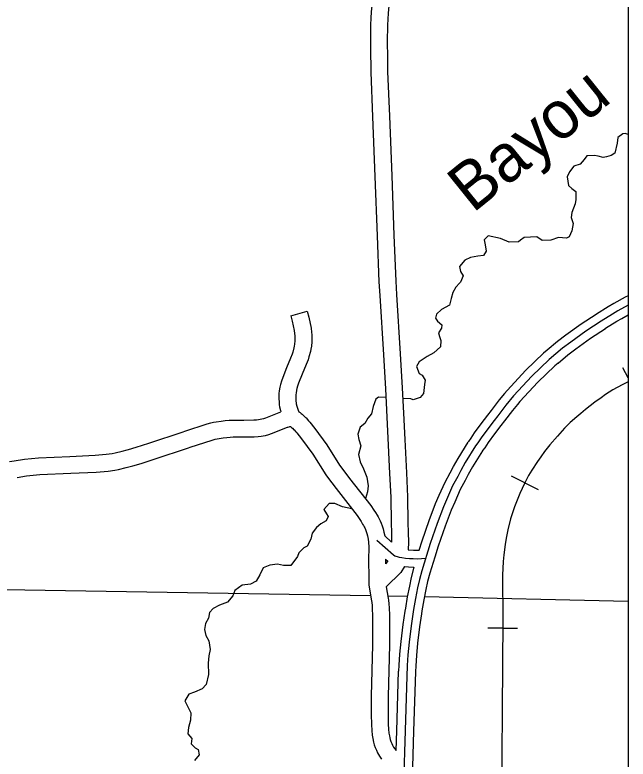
# Model space of a CAD drawing. Extents: x 1373094 to 1376427, y 1168361 to 1170494.
# Drawn here: x 1373889.9 to 1373980.6, y 1170144.1 to 1170254.2 of the extents above; entities that cross this region are included whole.
import ezdxf

# ---------------------------------------------------------------- set-up
doc = ezdxf.new("R2010")
doc.units = 0
doc.layers.add('R_Axis', color=7, linetype='Continuous')
doc.layers.add('R_No Plot', color=7, linetype='Continuous')

msp = doc.modelspace()

# ---------------------------------------------------------------- linework, layer by layer
at = {"layer": 'R_Axis'}
for p, q in [((1373930.68, 1170209.71), (1373933.09, 1170210.4)), ((1373977.22, 1170207.84), (1373977.22, 1170207.84)), ((1373980.59, 1170200.54), (1373979.83, 1170202.04)), ((1373965.3, 1170185), (1373963.34, 1170186)), ((1373965.3, 1170185), (1373967.26, 1170184)), ((1373962.04, 1170163.51), (1373959.84, 1170163.53)), ((1373962.04, 1170163.51), (1373964.24, 1170163.5))]:
    msp.add_line(p, q, dxfattribs=at)
for points in [[(1373942.8, 1170256.88), (1373942.59, 1170254.68), (1373942.53, 1170253.73), (1373942.48, 1170252.76), (1373942.46, 1170250.25), (1373942.48, 1170247.97)], [(1373945.29, 1170256.65), (1373945.08, 1170254.48), (1373945.02, 1170253.58), (1373944.98, 1170252.69), (1373944.96, 1170250.25), (1373944.98, 1170247.99)], [(1373942.48, 1170247.97), (1373942.48, 1170247.91), (1373942.5, 1170247.2), (1373942.51, 1170246.54), (1373942.51, 1170245.78), (1373942.77, 1170239.13)], [(1373944.98, 1170247.99), (1373944.98, 1170247.94), (1373944.99, 1170247.25), (1373945.01, 1170246.57), (1373945.01, 1170245.83), (1373945.27, 1170239.23)], [(1373945.27, 1170239.23), (1373945.61, 1170230.44)], [(1373942.77, 1170239.13), (1373943.11, 1170230.34)], [(1373980.59, 1170236.56), (1373980.17, 1170236.68), (1373979.82, 1170236.61), (1373979.08, 1170236.08), (1373978.95, 1170235.24), (1373978.63, 1170233.75), (1373978.09, 1170233.42), (1373977.38, 1170233.23), (1373976.88, 1170233.11), (1373976.16, 1170233.31), (1373975.63, 1170233.45), (1373974.46, 1170233.39), (1373974.09, 1170232.82), (1373973.49, 1170232.13), (1373972.55, 1170231.83), (1373971.92, 1170231.03), (1373971.58, 1170230.26), (1373971.79, 1170228.99), (1373972.25, 1170228.53), (1373972.84, 1170228.09), (1373972.83, 1170226.94), (1373972.78, 1170226.27), (1373972.24, 1170225.02), (1373972.17, 1170224.27), (1373972.46, 1170223.37), (1373972.28, 1170222.29), (1373971.87, 1170221.42), (1373971.49, 1170221.2), (1373970.29, 1170221.29), (1373969.18, 1170220.9), (1373967.89, 1170220.86), (1373967.08, 1170221.41), (1373965.2, 1170221.32), (1373964.69, 1170220.92), (1373964.35, 1170220.65), (1373962.97, 1170220.6), (1373961.72, 1170221.13), (1373959.88, 1170221.54), (1373959.31, 1170220.95), (1373959.43, 1170220.23), (1373959.6, 1170219.3), (1373959.18, 1170218.64), (1373958.33, 1170218.52), (1373957.26, 1170218.33), (1373956.43, 1170217.93), (1373955.64, 1170217.03), (1373955.8, 1170216.26), (1373956.2, 1170215.65), (1373955.8, 1170214.71), (1373955.62, 1170214.55), (1373955.09, 1170213.94), (1373954.65, 1170213.16), (1373954.42, 1170212.29), (1373954.14, 1170211.3), (1373952.97, 1170210.67), (1373952.22, 1170209.97), (1373952.07, 1170209.37), (1373952.38, 1170208.94), (1373953.01, 1170208.37), (1373953, 1170207.88), (1373952.55, 1170207.21), (1373952.66, 1170206.67), (1373952.87, 1170206.04), (1373952.81, 1170205.12), (1373951.85, 1170204.23), (1373950.88, 1170203.71)], [(1373945.61, 1170230.44), (1373945.95, 1170221.64)], [(1373943.11, 1170230.34), (1373943.45, 1170221.55)], [(1373945.95, 1170221.64), (1373946.21, 1170214.85), (1373946.33, 1170212.88)], [(1373943.45, 1170221.55), (1373943.72, 1170214.72), (1373943.84, 1170212.73)], [(1373946.33, 1170212.88), (1373946.87, 1170204.1)], [(1373943.84, 1170212.73), (1373944.38, 1170203.94)], [(1373980.59, 1170212.68), (1373980.15, 1170212.46), (1373978.47, 1170211.52), (1373977.63, 1170211.05), (1373975.9, 1170209.97), (1373975.84, 1170209.93)], [(1373980.59, 1170211.27), (1373979.08, 1170210.43), (1373978.27, 1170209.98), (1373976.58, 1170208.92), (1373974.33, 1170207.43), (1373972.12, 1170205.84), (1373970.9, 1170204.93), (1373968.92, 1170203.24), (1373966.35, 1170200.8), (1373963.63, 1170197.86), (1373962.5, 1170196.5), (1373961.31, 1170194.94), (1373960.78, 1170194.24), (1373959.82, 1170192.99), (1373958.85, 1170191.68), (1373958.34, 1170190.92), (1373958.01, 1170190.46), (1373956.5, 1170188), (1373955.84, 1170186.82), (1373955.38, 1170185.93), (1373954.63, 1170184.57), (1373953.25, 1170181.46), (1373952.35, 1170179.01), (1373951.31, 1170176.03), (1373950.05, 1170171.99), (1373949.71, 1170170.7), (1373949.44, 1170169.48), (1373949.13, 1170167.91), (1373948.86, 1170166.25), (1373948.49, 1170163.88), (1373948.18, 1170161.43), (1373948.01, 1170159.59), (1373947.92, 1170158), (1373947.05, 1170130.79)], [(1373930.68, 1170209.71), (1373930.9, 1170208.94), (1373931.2, 1170207.52), (1373931.24, 1170207.09), (1373931.27, 1170206.73), (1373931.29, 1170206.4), (1373931.28, 1170206), (1373931.24, 1170205.53), (1373931.19, 1170205.25), (1373931.14, 1170204.98), (1373930.97, 1170204.35), (1373930.86, 1170204.03), (1373930.64, 1170203.44), (1373930.05, 1170202.02)], [(1373933.09, 1170210.4), (1373933.33, 1170209.54), (1373933.68, 1170207.9), (1373933.74, 1170207.31), (1373933.77, 1170206.89), (1373933.79, 1170206.44), (1373933.78, 1170205.87), (1373933.72, 1170205.21), (1373933.65, 1170204.8), (1373933.58, 1170204.42), (1373933.36, 1170203.63), (1373933.23, 1170203.21), (1373932.96, 1170202.52), (1373932.37, 1170201.07)], [(1373975.84, 1170209.93), (1373973.62, 1170208.46), (1373971.38, 1170206.85), (1373970.12, 1170205.91), (1373968.63, 1170204.63)], [(1373977.22, 1170207.84), (1373977.25, 1170207.87), (1373978.91, 1170208.9), (1373979.68, 1170209.34), (1373980.59, 1170209.84)], [(1373970.25, 1170202.73), (1373971.69, 1170203.95), (1373972.86, 1170204.83), (1373975.04, 1170206.4), (1373977.22, 1170207.84)], [(1373946.87, 1170204.1), (1373947.18, 1170199.07), (1373947.37, 1170195.3)], [(1373968.63, 1170204.63), (1373968.09, 1170204.17), (1373965.46, 1170201.68), (1373962.69, 1170198.69), (1373962.31, 1170198.23)], [(1373944.38, 1170203.94), (1373944.68, 1170198.93), (1373945.29, 1170186.39)], [(1373950.88, 1170203.71), (1373949.69, 1170202.9), (1373949.26, 1170202.22), (1373949.68, 1170201.18), (1373950.12, 1170200.92), (1373950.58, 1170200.2), (1373950.48, 1170199.54), (1373950.33, 1170198.24), (1373949.84, 1170197.63), (1373948.78, 1170197.27), (1373948.44, 1170197.46), (1373947.26, 1170197.5)], [(1373930.05, 1170202.02), (1373929.48, 1170200.61), (1373929.28, 1170200.03), (1373929.15, 1170199.58), (1373929.07, 1170199.18), (1373928.97, 1170198.63), (1373928.93, 1170198.21), (1373928.92, 1170197.47), (1373928.95, 1170196.93), (1373928.98, 1170196.57), (1373929.03, 1170196.23), (1373929.15, 1170195.73), (1373929.21, 1170195.52)], [(1373970.25, 1170202.73), (1373969.76, 1170202.31), (1373967.24, 1170199.92), (1373964.57, 1170197.04), (1373964.23, 1170196.62)], [(1373932.37, 1170201.07), (1373931.82, 1170199.73), (1373931.67, 1170199.29), (1373931.58, 1170198.98), (1373931.52, 1170198.71), (1373931.45, 1170198.28), (1373931.43, 1170198.06), (1373931.42, 1170197.53), (1373931.44, 1170197.1), (1373931.46, 1170196.86), (1373931.49, 1170196.71), (1373931.56, 1170196.37), (1373931.66, 1170196.05), (1373931.78, 1170195.74), (1373931.88, 1170195.49)], [(1373980.59, 1170199.96), (1373979.73, 1170199.52), (1373978.33, 1170198.76), (1373977.25, 1170198.06), (1373976.59, 1170197.6), (1373975.66, 1170196.92), (1373974.97, 1170196.41), (1373974.28, 1170195.85), (1373973.59, 1170195.28), (1373973.02, 1170194.79), (1373972.04, 1170193.92), (1373971.17, 1170193.09), (1373970.13, 1170191.93), (1373969.01, 1170190.63), (1373968.23, 1170189.65), (1373967.67, 1170188.87), (1373967.16, 1170188.15), (1373966.32, 1170186.88), (1373965.85, 1170186.08), (1373965.27, 1170184.93), (1373964.58, 1170183.43), (1373963.78, 1170181.44), (1373963.2, 1170179.68), (1373962.79, 1170178.08), (1373962.54, 1170176.84), (1373962.38, 1170175.91), (1373962.2, 1170174.35), (1373962.11, 1170173.36), (1373961.98, 1170171.34), (1373962.05, 1170164.74), (1373961.81, 1170131.3)], [(1373980.59, 1170199.96), (1373979.73, 1170199.52), (1373978.33, 1170198.76), (1373977.25, 1170198.06), (1373976.59, 1170197.6), (1373975.66, 1170196.92), (1373974.97, 1170196.41), (1373974.28, 1170195.85)], [(1373944.75, 1170197.62), (1373943.65, 1170197.7), (1373943.25, 1170197.39), (1373942.86, 1170196.29), (1373942.63, 1170195.22), (1373942.07, 1170194.56), (1373941.63, 1170193.78), (1373940.93, 1170193.26), (1373940.62, 1170192.2), (1373940.77, 1170191.41), (1373941.02, 1170190.46), (1373940.7, 1170189.2), (1373940.95, 1170188.12), (1373941.46, 1170187.06), (1373941.93, 1170185.87), (1373942.13, 1170184.55), (1373942.05, 1170183.7), (1373941.71, 1170182.67)], [(1373962.31, 1170198.23), (1373961.52, 1170197.28), (1373960.32, 1170195.7), (1373959.79, 1170195), (1373958.82, 1170193.74), (1373957.83, 1170192.4), (1373957.31, 1170191.63), (1373956.97, 1170191.14), (1373956.91, 1170191.05)], [(1373964.23, 1170196.62), (1373963.47, 1170195.72), (1373962.31, 1170194.18), (1373961.77, 1170193.48), (1373960.82, 1170192.24), (1373959.87, 1170190.96), (1373959.37, 1170190.21), (1373959.06, 1170189.77), (1373959.04, 1170189.74)], [(1373923.71, 1170194.3), (1373925.2, 1170194.32), (1373925.61, 1170194.34), (1373925.91, 1170194.38), (1373926.16, 1170194.43), (1373926.4, 1170194.47), (1373926.69, 1170194.55), (1373926.98, 1170194.64), (1373929.21, 1170195.52)], [(1373931.88, 1170195.49), (1373932.05, 1170195.39), (1373932.2, 1170195.28), (1373932.37, 1170195.15), (1373932.58, 1170194.96), (1373932.88, 1170194.68)], [(1373947.37, 1170195.3), (1373947.56, 1170191.41), (1373947.79, 1170186.5)], [(1373974.28, 1170195.85), (1373973.59, 1170195.28), (1373973.02, 1170194.79), (1373972.04, 1170193.92), (1373971.17, 1170193.09), (1373970.13, 1170191.93), (1373969.01, 1170190.63), (1373968.23, 1170189.65), (1373967.67, 1170188.87), (1373967.16, 1170188.15), (1373966.32, 1170186.88), (1373965.85, 1170186.08), (1373965.27, 1170184.93), (1373964.58, 1170183.43), (1373963.78, 1170181.44), (1373963.2, 1170179.68), (1373962.79, 1170178.08), (1373962.54, 1170176.84), (1373962.38, 1170175.91), (1373962.2, 1170174.35), (1373962.11, 1170173.36), (1373961.98, 1170171.34), (1373962.05, 1170164.74), (1373961.81, 1170131.3)], [(1373914.76, 1170192.57), (1373915, 1170192.65), (1373918.31, 1170193.72), (1373918.85, 1170193.87), (1373919.22, 1170193.96), (1373919.65, 1170194.05), (1373920.37, 1170194.15), (1373920.98, 1170194.22), (1373921.54, 1170194.26), (1373922.06, 1170194.29), (1373922.81, 1170194.3), (1373923.04, 1170194.29), (1373923.29, 1170194.3), (1373923.71, 1170194.3)], [(1373932.88, 1170194.68), (1373932.95, 1170194.61), (1373933.32, 1170194.2), (1373933.5, 1170193.99), (1373934.24, 1170193.04), (1373936.01, 1170190.65), (1373937.9, 1170187.62), (1373938.1, 1170187.36)], [(1373923.74, 1170191.8), (1373925.28, 1170191.82), (1373925.84, 1170191.85), (1373926.28, 1170191.91), (1373926.6, 1170191.97), (1373926.96, 1170192.03), (1373927.41, 1170192.16), (1373927.82, 1170192.29), (1373930.2, 1170193.23), (1373930.23, 1170193.24), (1373930.42, 1170193.3), (1373930.56, 1170193.32), (1373930.59, 1170193.32), (1373930.64, 1170193.32), (1373930.68, 1170193.29), (1373930.78, 1170193.21), (1373930.91, 1170193.11), (1373931.15, 1170192.87)], [(1373906.46, 1170189.89), (1373906.65, 1170189.94), (1373907.79, 1170190.27), (1373909.68, 1170190.87), (1373914.76, 1170192.57)], [(1373931.15, 1170192.87), (1373931.16, 1170192.86), (1373931.43, 1170192.57), (1373931.55, 1170192.42), (1373932.26, 1170191.53), (1373933.94, 1170189.24), (1373935.84, 1170186.21), (1373936.1, 1170185.86)], [(1373915.55, 1170190.2), (1373915.78, 1170190.28), (1373919.03, 1170191.32), (1373919.49, 1170191.45), (1373919.77, 1170191.52), (1373920.08, 1170191.58), (1373920.68, 1170191.67), (1373921.2, 1170191.73), (1373921.7, 1170191.76), (1373922.16, 1170191.79), (1373922.77, 1170191.8), (1373923.01, 1170191.79), (1373923.33, 1170191.8), (1373923.74, 1170191.8)], [(1373952.65, 1170183.18), (1373953.51, 1170185.12), (1373954.28, 1170186.51), (1373954.74, 1170187.41), (1373955.42, 1170188.63), (1373956.91, 1170191.05)], [(1373898.01, 1170188.93), (1373901.75, 1170189.11), (1373903.37, 1170189.24), (1373904.23, 1170189.36), (1373904.7, 1170189.45), (1373905.71, 1170189.69), (1373906.46, 1170189.89)], [(1373907.1, 1170187.47), (1373907.33, 1170187.53), (1373908.52, 1170187.88), (1373910.45, 1170188.49), (1373915.55, 1170190.2)], [(1373959.04, 1170189.74), (1373957.58, 1170187.37), (1373956.94, 1170186.23), (1373956.48, 1170185.34), (1373955.76, 1170184.01), (1373954.93, 1170182.16)], [(1373889.08, 1170188.16), (1373889.77, 1170188.28), (1373891.27, 1170188.51), (1373893.35, 1170188.71), (1373898.01, 1170188.93)], [(1373898.12, 1170186.43), (1373901.9, 1170186.61), (1373903.65, 1170186.75), (1373904.63, 1170186.9), (1373905.21, 1170187), (1373906.32, 1170187.26), (1373907.1, 1170187.47)], [(1373890.18, 1170185.82), (1373891.58, 1170186.03), (1373893.53, 1170186.22), (1373898.12, 1170186.43)], [(1373938.1, 1170187.36), (1373939.37, 1170185.67), (1373942.5, 1170181.66), (1373942.98, 1170180.96), (1373943.2, 1170180.61), (1373943.44, 1170180.23)], [(1373945.29, 1170186.39), (1373945.46, 1170182.87), (1373945.52, 1170179.1), (1373945.56, 1170177.62)], [(1373947.79, 1170186.5), (1373947.96, 1170182.95), (1373948.02, 1170179.16), (1373948.06, 1170177.68)], [(1373936.1, 1170185.86), (1373937.38, 1170184.15), (1373940.48, 1170180.18), (1373940.89, 1170179.58), (1373941.09, 1170179.28), (1373941.31, 1170178.91)], [(1373949.69, 1170175.04), (1373950.13, 1170176.43), (1373951.17, 1170179.43), (1373952.09, 1170181.94), (1373952.65, 1170183.18)], [(1373939.7, 1170181.18), (1373938.35, 1170181.48), (1373937.21, 1170181.96), (1373936.38, 1170181.94), (1373935.56, 1170181.09), (1373935.96, 1170180.44), (1373936.22, 1170180.05), (1373935.93, 1170179.41), (1373935.11, 1170178.97), (1373934.47, 1170178.41), (1373933.85, 1170177.56), (1373933.64, 1170176.69), (1373933.11, 1170175.64), (1373932.62, 1170175.41), (1373931.85, 1170174.66), (1373931.68, 1170174.09), (1373930.68, 1170172.8), (1373929.61, 1170172.79), (1373928.71, 1170172.99), (1373927.6, 1170172.84), (1373926.61, 1170172.46), (1373926.11, 1170171.42), (1373925.58, 1170170.47), (1373924.71, 1170170.04), (1373923.5, 1170169.86), (1373922.4, 1170169.07), (1373922.1, 1170168.31), (1373921.31, 1170167.34), (1373920.15, 1170166.92), (1373919.21, 1170166.41), (1373918.66, 1170165.82), (1373918.49, 1170164.99), (1373918.06, 1170164.22), (1373917.91, 1170163.33), (1373918.13, 1170162.41), (1373918.55, 1170161.62), (1373918.76, 1170160.37), (1373918.53, 1170159.4), (1373918.47, 1170158.33), (1373918.52, 1170156.67), (1373918.17, 1170155.16), (1373917.58, 1170154.53), (1373916.43, 1170154.06), (1373915.57, 1170153.76), (1373914.98, 1170152.76), (1373915.9, 1170150.97), (1373915.82, 1170149.92), (1373915.53, 1170148.81), (1373915.43, 1170147.87), (1373916.03, 1170147.2), (1373915.96, 1170146.4), (1373916.54, 1170145.79), (1373916.97, 1170145.58), (1373917.12, 1170144.8), (1373916.41, 1170143.95)], [(1373954.93, 1170182.16), (1373954.41, 1170180.99), (1373953.52, 1170178.59), (1373952.5, 1170175.64), (1373951.99, 1170174.02)], [(1373943.44, 1170180.23), (1373943.6, 1170179.97), (1373943.76, 1170179.68), (1373943.89, 1170179.41), (1373944.06, 1170179.04), (1373944.21, 1170178.64), (1373944.35, 1170178.2), (1373944.47, 1170177.71), (1373944.58, 1170177.16)], [(1373941.31, 1170178.91), (1373941.44, 1170178.7), (1373941.54, 1170178.52), (1373941.63, 1170178.35), (1373941.74, 1170178.09), (1373941.85, 1170177.8), (1373941.95, 1170177.5), (1373942.03, 1170177.17), (1373942.13, 1170176.68), (1373942.19, 1170176.21), (1373942.24, 1170175.51), (1373942.19, 1170173.6), (1373942.22, 1170170.96)], [(1373945.56, 1170177.62), (1373945.6, 1170176.25)], [(1373948.06, 1170177.68), (1373948.1, 1170176.24), (1373948.07, 1170175.1)], [(1373943.41, 1170176.53), (1373945.86, 1170174.34), (1373946.07, 1170174.22), (1373946.23, 1170174.16), (1373946.42, 1170174.09), (1373946.7, 1170174.02), (1373947.09, 1170173.96), (1373947.66, 1170173.89), (1373948.22, 1170173.84), (1373948.79, 1170173.81), (1373949.38, 1170173.79), (1373950.64, 1170173.88)], [(1373944.58, 1170177.16), (1373945.6, 1170176.25)], [(1373948.07, 1170175.1), (1373948.84, 1170175.05), (1373949.69, 1170175.04)], [(1373944.68, 1170173.72), (1373945.04, 1170173.4)], [(1373944.68, 1170173.72), (1373944.69, 1170173.04)], [(1373945.04, 1170173.4), (1373944.69, 1170173.04)], [(1373951.99, 1170174.02), (1373951.25, 1170171.65), (1373950.92, 1170170.41), (1373950.67, 1170169.22), (1373950.36, 1170167.69), (1373950.09, 1170166.06), (1373950.03, 1170165.65)], [(1373947.52, 1170172.65), (1373946.94, 1170171.75), (1373944.8, 1170169.62)], [(1373947.52, 1170172.65), (1373948.12, 1170172.59), (1373948.9, 1170172.55)], [(1373948.9, 1170172.55), (1373948.49, 1170170.99), (1373948.22, 1170169.73), (1373947.9, 1170168.14), (1373947.63, 1170166.45), (1373947.56, 1170166.03)], [(1373942.22, 1170170.96), (1373942.24, 1170169.85), (1373942.6, 1170167.56), (1373942.65, 1170167.3), (1373942.7, 1170166.86), (1373942.74, 1170166.38), (1373942.76, 1170165.41), (1373942.76, 1170164.5), (1373942.77, 1170163.42), (1373942.77, 1170162.21)], [(1373870.23, 1170169.54), (1373942.48, 1170168.34)], [(1373944.8, 1170169.62), (1373945.07, 1170167.96), (1373945.12, 1170167.65), (1373945.19, 1170167.1), (1373945.23, 1170166.5), (1373945.26, 1170165.45), (1373945.26, 1170164.51), (1373945.27, 1170163.42), (1373945.27, 1170162.21)], [(1373945.02, 1170168.3), (1373947.92, 1170168.25)], [(1373950.45, 1170168.22), (1373980.59, 1170167.52)], [(1373947.56, 1170166.03), (1373947.25, 1170164.06), (1373946.94, 1170161.56), (1373946.76, 1170159.68), (1373946.67, 1170158.06), (1373946.64, 1170157.14)], [(1373950.03, 1170165.65), (1373949.73, 1170163.71), (1373949.43, 1170161.29), (1373949.26, 1170159.49), (1373949.17, 1170157.95), (1373949.14, 1170157.06)], [(1373942.77, 1170162.21), (1373942.77, 1170161.06), (1373942.59, 1170153.44)], [(1373945.27, 1170162.21), (1373945.27, 1170161.03), (1373945.09, 1170153.39)], [(1373946.36, 1170148.34), (1373946.64, 1170157.14)], [(1373949.14, 1170157.06), (1373948.86, 1170148.26)], [(1373942.59, 1170153.44), (1373942.58, 1170153.17), (1373942.59, 1170150.74), (1373942.6, 1170149.24), (1373942.65, 1170148.36), (1373942.73, 1170147.67), (1373942.8, 1170147.18), (1373942.9, 1170146.67), (1373943.02, 1170146.26), (1373943.17, 1170145.85), (1373943.34, 1170145.45), (1373943.5, 1170145.08), (1373943.79, 1170144.57), (1373944.1, 1170144.14)], [(1373945.09, 1170153.39), (1373945.08, 1170153.14), (1373945.09, 1170150.75), (1373945.1, 1170149.32), (1373945.14, 1170148.58), (1373945.21, 1170147.99), (1373945.26, 1170147.6), (1373945.33, 1170147.29), (1373945.4, 1170147.03), (1373945.5, 1170146.76), (1373945.63, 1170146.45), (1373945.74, 1170146.21), (1373945.9, 1170145.93), (1373946.26, 1170145.42)], [(1373946.26, 1170145.42), (1373946.36, 1170148.34)], [(1373948.86, 1170148.26), (1373948.58, 1170139.46)], [(1373946.13, 1170145.61), (1373946.13, 1170145.6), (1373946.27, 1170145.46)]]:
    msp.add_lwpolyline(points, dxfattribs=at)
at = {"layer": 'R_No Plot'}
msp.add_lwpolyline([(1373251.19, 1170420.71), (1373980.59, 1170420.71), (1373980.59, 1169636.22), (1373251.19, 1169636.22)], close=True, dxfattribs=at)

# ---------------------------------------------------------------- texts
at = {"layer": 'R_Axis'}
msp.add_text('Bayou', height=7.04, rotation=38.8084, dxfattribs=at).set_placement((1373957.6, 1170224.81))

doc.saveas('drawing.dxf')
